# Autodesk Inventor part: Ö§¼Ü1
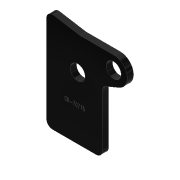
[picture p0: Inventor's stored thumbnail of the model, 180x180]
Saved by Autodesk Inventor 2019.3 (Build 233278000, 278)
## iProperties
Created: 2017-10
Part Number: Ö§¼Ü1
Material: Ogólny
Document SubType Name: Modeling
Designer: CADENGINEERING4
Density: 1 g/cm^3
Appearance: Gładki — czarny
Author: CADENGINEERING4
Revision Number: ÈÎºÎ
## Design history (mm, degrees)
feature "ÇÐ³ý-À­Éì1"
node "Bryła1"
